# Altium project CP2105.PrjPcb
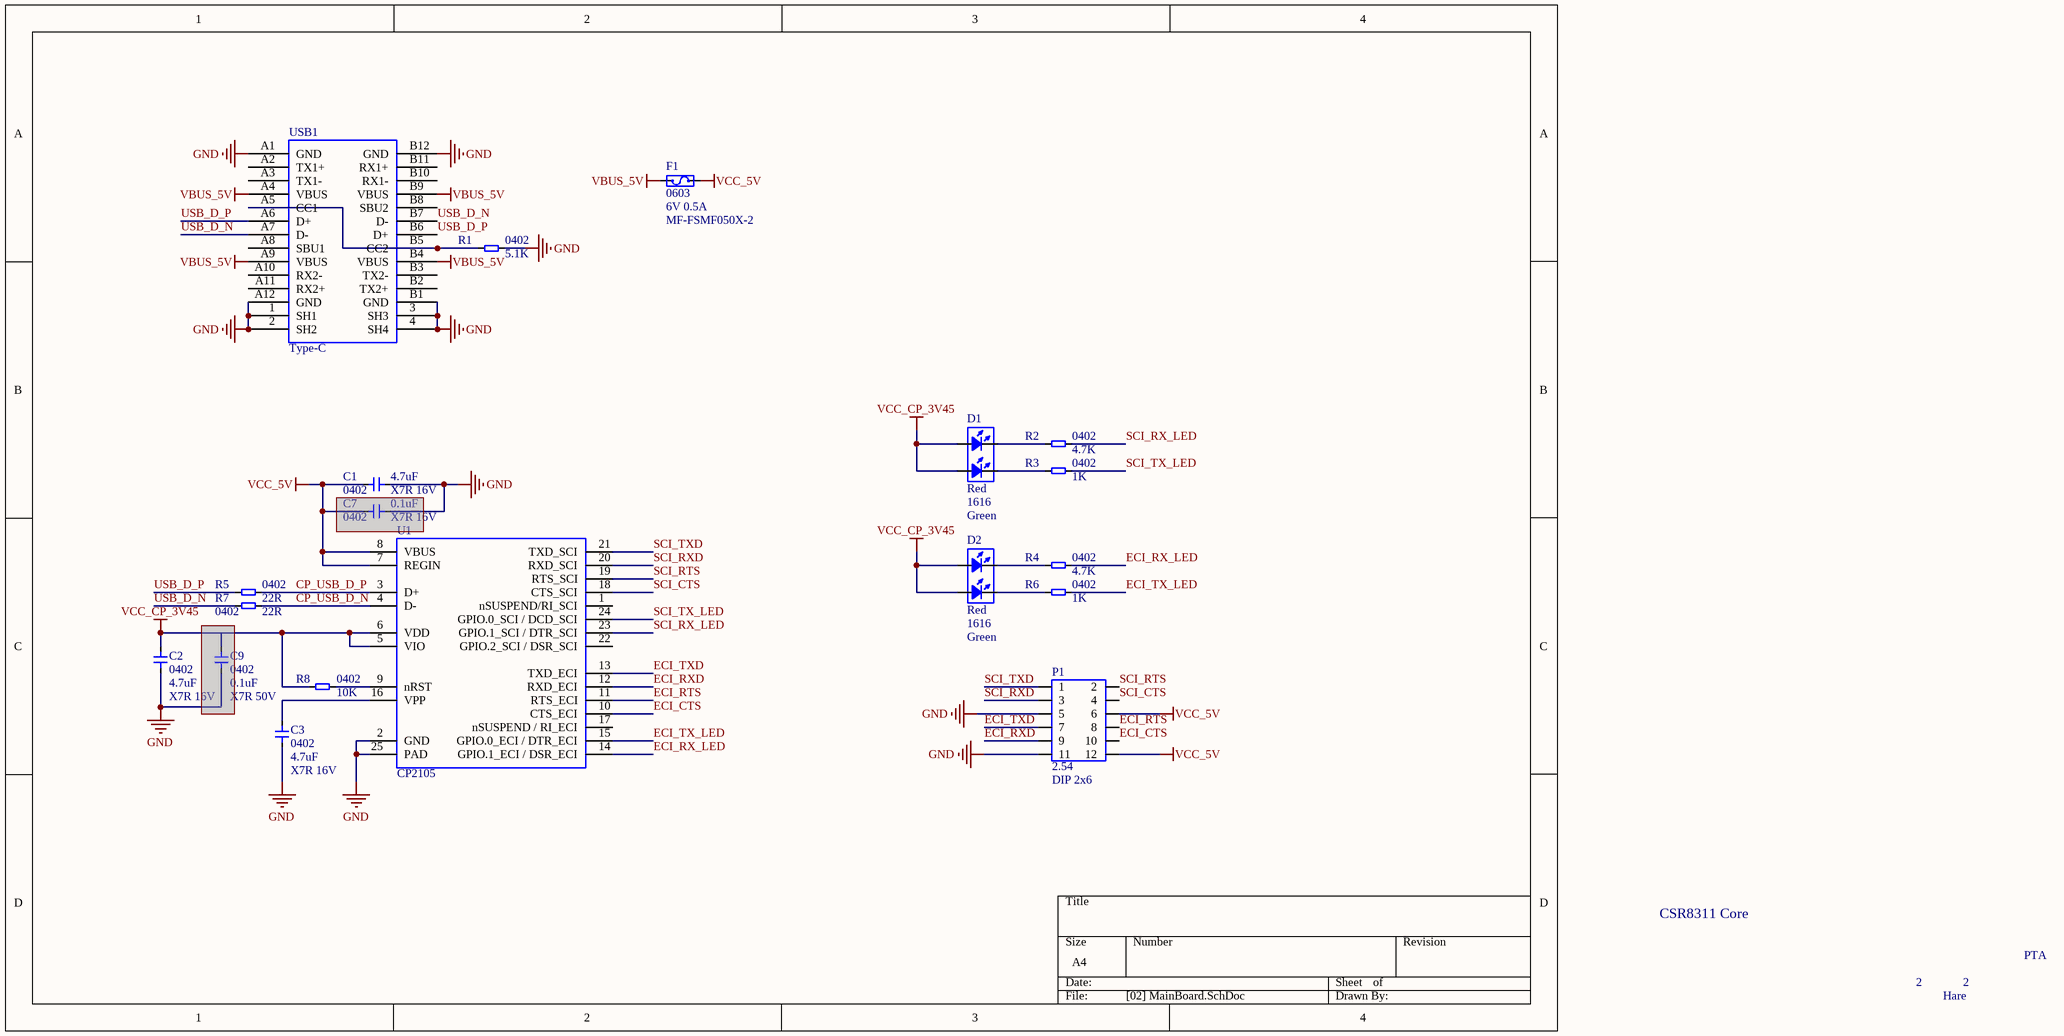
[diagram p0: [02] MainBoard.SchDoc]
1 sheet, 19 parts. Net scope: global (net labels, ports and power ports of the same name join across sheets).
Board file: CP2105.PcbDoc

## Sheet [02] MainBoard.SchDoc
size A4

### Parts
C1  Footprint: 0402  Specification: X7R 16V  [CAP_0402]  (hidden comment: 4.7uF)
C2  Footprint: 0402  Specification: X7R 16V  [CAP_0402]  (hidden comment: 4.7uF)
C3  Footprint: 0402  Specification: X7R 16V  [CAP_0402]  (hidden comment: 4.7uF)
C7  Footprint: 0402  Specification: X7R 16V  [CAP_0402]  (hidden comment: 0.1uF)  (masked out: inside a compile mask, not in the netlist)
C9  Footprint: 0402  Specification: X7R 50V  [CAP_0402]  (hidden comment: 0.1uF)  (masked out: inside a compile mask, not in the netlist)
D1  Value2: Red  Footprint: 1616  Value1: Green  [LED_1616]
D2  Value2: Red  Footprint: 1616  Value1: Green  [LED_1616]
F1  Footprint: 0603  Specification: 6V 0.5A  [FUSE_0603]  (hidden comment: MF-FSMF050X-2)
P1  Type: 2.54  [HDR2X6_2.54_180H]  (hidden comment: DIP 2x6)
R1  Footprint: 0402  [RES_0402]  (hidden comment: 5.1K)
R2  Footprint: 0402  [RES_0402]  (hidden comment: 4.7K)
R3  Footprint: 0402  [RES_0402]  (hidden comment: 1K)
R4  Footprint: 0402  [RES_0402]  (hidden comment: 4.7K)
R5  Footprint: 0402  [RES_0402]  (hidden comment: 22R)
R6  Footprint: 0402  [RES_0402]  (hidden comment: 1K)
R7  Footprint: 0402  [RES_0402]  (hidden comment: 22R)
R8  Footprint: 0402  [RES_0402]  (hidden comment: 10K)
U1  CP2105  [QFN-24-4.0X4.0-P0.5]
USB1  Type-C  [USB-Type-C]

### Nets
GND: C1.2 C2.2 C3.2 P1.5 P1.11 R1.1 U1.2(GND) U1.25(PAD) USB1.1(SH1) USB1.2(SH2) USB1.3(SH3) USB1.4(SH4) USB1.A1(GND) USB1.A12(GND) USB1.B1(GND) USB1.B12(GND)
VBUS_5V: F1.1 USB1.A4(VBUS) USB1.A9(VBUS) USB1.B4(VBUS) USB1.B9(VBUS)
VCC_5V: C1.1 F1.2 P1.6 P1.12 U1.7(REGIN) U1.8(VBUS)
VCC_CP_3V45: C2.1 D1.3 D1.4 D2.3 D2.4 R8.1 U1.5(VIO) U1.6(VDD)
CP_USB_D_N: R7.1 U1.4(D-)
CP_USB_D_P: R5.1 U1.3(D+)
ECI_CTS: P1.10 U1.10(CTS_ECI)
ECI_RTS: P1.8 U1.11(RTS_ECI)
ECI_RX_LED: R4.1 U1.14(GPIO.1_ECI_/_DSR_ECI)
ECI_RXD: P1.9 U1.12(RXD_ECI)
ECI_TX_LED: R6.1 U1.15(GPIO.0_ECI_/_DTR_ECI)
ECI_TXD: P1.7 U1.13(TXD_ECI)
SCI_CTS: P1.4 U1.18(CTS_SCI)
SCI_RTS: P1.2 U1.19(RTS_SCI)
SCI_RX_LED: R2.1 U1.23(GPIO.1_SCI_/_DTR_SCI)
SCI_RXD: P1.3 U1.20(RXD_SCI)
SCI_TX_LED: R3.1 U1.24(GPIO.0_SCI_/_DCD_SCI)
SCI_TXD: P1.1 U1.21(TXD_SCI)
USB_D_N: R7.2 USB1.A7(D-) USB1.B7(D-)
USB_D_P: R5.2 USB1.A6(D+) USB1.B6(D+)
NetC3_1: C3.1 U1.16(VPP)
NetD1_1: D1.1 R2.2
NetD1_2: D1.2 R3.2
NetD2_1: D2.1 R4.2
NetD2_2: D2.2 R6.2
NetR1_2: R1.2 USB1.A5(CC1) USB1.B5(CC2)
NetR8_2: R8.2 U1.9(nRST)

Not connected (* = marked no-connect by the designer): U1 1(nSUSPEND/RI_SCI) 17(nSUSPEND_/_RI_ECI) 22(GPIO.2_SCI_/_DSR_SCI); USB1 A2(TX1+) A3(TX1-) A8(SBU1) A10(RX2-) A11(RX2+) B2(TX2+) B3(TX2-) B8(SBU2) B10(RX1-) B11(RX1+)

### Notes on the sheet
- CSR8311 Core
- 2
- PTA
- Hare

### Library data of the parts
C1-C3 C7 C9 = CAP: Capacitor
D1 D2 = LEDx2: LED双色
F1 = Fuse
P1 = HDR2x6: Header
R1-R8 = RES: Resistor; Specification: ±1%
U1 = CP2105: Single-Chip USB to Dual UART Data Transfer
USB1 = USB-Type-C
